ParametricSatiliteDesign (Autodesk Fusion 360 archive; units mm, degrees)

design "Assambly" references "SolarPanelWing", "SidePanelWithWingCutOut", "SidePanel", "TopandBottomPanel"
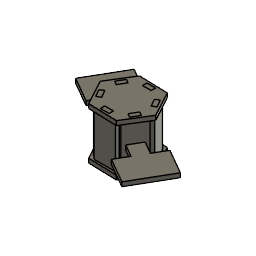
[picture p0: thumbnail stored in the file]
part number: 2026-03-25-13-54-13-246
component_insert "Component Insert1"
component_insert "Component Insert2"
joint "Assemble2" alignAngle 180 alignOffsetX 0 alignOffsetY -3 alignOffsetZ 0
component_insert "Component Insert3"
joint "Assemble3" alignAngle 180 alignOffsetX 0 alignOffsetY -3 alignOffsetZ 0
component_insert "Component Insert4"
joint "Assemble4" alignAngle 180 alignOffsetX 0 alignOffsetY -3 alignOffsetZ 0
component_insert "Component Insert6"
joint "Assemble6" alignAngle 180 alignOffsetX 0 alignOffsetY -3 alignOffsetZ 0
component_insert "Component Insert7"
joint "Assemble7" alignAngle 180 alignOffsetX 0 alignOffsetY -3 alignOffsetZ 0
component_insert "Component Insert9"
component_insert "Component Insert10"
joint "Assemble10" alignAngle 180 alignOffsetX 0 alignOffsetY -3 alignOffsetZ 0
component_insert "Component Insert11"
joint "Assemble11" alignAngle 180 alignOffsetX 0 alignOffsetY 0 alignOffsetZ 0
joint "Assemble12" alignAngle 0 alignOffsetX 0 alignOffsetY 3 alignOffsetZ 0
component_insert "Component Insert12"
joint "Assemble13" alignAngle -180 alignOffsetX 0 alignOffsetY 0 alignOffsetZ 0
component_insert "Component Insert13"
joint "Assemble14" alignAngle 0 alignOffsetX 0 alignOffsetY 0 alignOffsetZ 0

design "SidePanel"
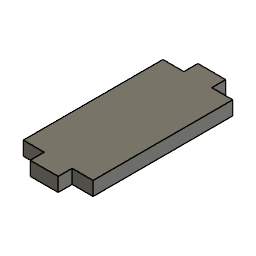
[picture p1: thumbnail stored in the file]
part number: 2026-03-25-13-26-19-886
parameter "BaseRectangleW" = 15
parameter "BaseRectangileH" = 30
parameter "MaterialThickness" = 3
parameter "JointW" = 6
sketch "Sketch1" plane through (0, 0, 0) normal (0, 1, 0) x axis (1, 0, 0)
  line L1 (15, 0) -> (0, 0)
  line L2 (15, 30) -> (15, 0)
  line L3 (0, 30) -> (15, 30)
  line L4 (0, 0) -> (0, 30)
  line L5 (10.5, 30) -> (4.5, 30)
  line L6 (10.5, 33) -> (10.5, 30)
  line L7 (4.5, 33) -> (10.5, 33)
  line L8 (4.5, 30) -> (4.5, 33)
  line L9 (10.5, 0) -> (4.5, 0)
  line L10 (10.5, -3) -> (10.5, 0)
  line L11 (4.5, -3) -> (10.5, -3)
  line L12 (4.5, 0) -> (4.5, -3)
  point P1 (0, 0)
  point P2 (0, 0)
  point P6 (4.5, 30)
  point P10 (4.5, 0)
  point P3 (15, 0)
  point P5 (0, 30)
  point P9 (4.5, 33)
  point P8 (10.5, 33)
  point P13 (4.5, -3)
  point P12 (10.5, -3)
  horizontal L1
  vertical L2
  horizontal L3
  vertical L4
  coincident P1 P2
  horizontal L5
  vertical L6
  horizontal L7
  vertical L8
  coincident L3 P6
  midpoint L3 L5
  horizontal L9
  vertical L10
  horizontal L11
  vertical L12
  coincident L1 P10
  midpoint L1 L9
  dimension "d5" distance P2 P3 = 15 (= "BaseRectangleW")
  dimension "d6" distance P2 P5 = 30 (= "BaseRectangileH")
  dimension "d7" distance P6 P9 = 3 (= "MaterialThickness")
  dimension "d8" distance P8 P9 = 6 (= "JointW")
  dimension "d9" distance P10 P13 = 3 (= "MaterialThickness")
  dimension "d10" distance P12 P13 = 6 (= "JointW")
extrude "Extrude1" new body sketch "Sketch1" along normal blind 3

design "TopandBottomPanel"
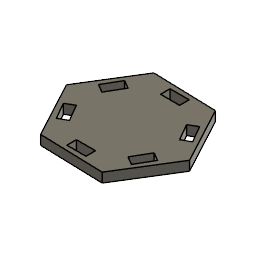
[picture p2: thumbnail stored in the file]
part number: 2026-03-25-13-47-20-194
parameter "PolygonSideW" = 20
parameter "MaterialThickness" = 3
sketch "Sketch1" plane through (0, 0, 0) normal (0, 1, 0) x axis (1, 0, 0)
  line L1 (19.9909, -0.602) -> (0, 0)
  line L2 (30.5078, 16.4096) -> (19.9909, -0.602)
  line L3 (21.0336, 34.0233) -> (30.5078, 16.4096)
  line L4 (1.0427, 34.6253) -> (21.0336, 34.0233)
  line L5 (-9.4741, 17.6137) -> (1.0427, 34.6253)
  line L6 (0, 0) -> (-9.4741, 17.6137)
  line L7 (10.0858, 2.699) -> (9.9955, -0.301)
  line L8 (7.0858, 4.199) -> (13.0858, 4.199)
  line L9 (7.0858, 1.199) -> (7.0858, 4.199)
  line L10 (13.0858, 1.199) -> (7.0858, 1.199)
  line L11 (13.0858, 4.199) -> (13.0858, 1.199)
  line L12 (7.0858, 1.199) -> (13.0858, 4.199)
  line L13 (13.0858, 1.199) -> (7.0858, 4.199)
  line L14 (22.8974, 12.8301) -> (25.4955, 11.3301)
  line L15 (25.4955, 11.3301) -> (22.4955, 6.134)
  line L16 (22.4955, 6.134) -> (19.8974, 7.634)
  line L17 (19.8974, 7.634) -> (22.8974, 12.8301)
  line L18 (20.3284, 25.6428) -> (22.9265, 27.1428)
  line L19 (22.9265, 27.1428) -> (25.9265, 21.9466)
  line L20 (25.9265, 21.9466) -> (23.3284, 20.4466)
  line L21 (23.3284, 20.4466) -> (20.3284, 25.6428)
  line L22 (7.9478, 29.8243) -> (7.9478, 32.8243)
  line L23 (7.9478, 32.8243) -> (13.9478, 32.8243)
  line L24 (13.9478, 32.8243) -> (13.9478, 29.8243)
  line L25 (13.9478, 29.8243) -> (7.9478, 29.8243)
  line L26 (-1.8638, 21.1932) -> (-4.4618, 22.6932)
  line L27 (-4.4618, 22.6932) -> (-1.4618, 27.8893)
  line L28 (-1.4618, 27.8893) -> (1.1362, 26.3893)
  line L29 (1.1362, 26.3893) -> (-1.8638, 21.1932)
  line L30 (0.7052, 8.3805) -> (-1.8928, 6.8805)
  line L31 (-1.8928, 6.8805) -> (-4.8928, 12.0767)
  line L32 (-4.8928, 12.0767) -> (-2.2948, 13.5767)
  line L33 (-2.2948, 13.5767) -> (0.7052, 8.3805)
  point P1 (0, 0)
  point P2 (0, 0)
  point P9 (9.9955, -0.301)
  point P15 (10.0858, 2.699)
  point P10 (10.0858, 2.699)
  point P3 (19.9909, -0.602)
  point P13 (7.0858, 1.199)
  point P14 (13.0858, 1.199)
  point P12 (7.0858, 4.199)
  coincident P1 P2
  coincident L1 P9
  perpendicular L1 L7
  midpoint L1 P9
  horizontal L8
  perpendicular L8 L9
  parallel L8 L10
  parallel L9 L11
  coincident L12 P15
  coincident L13 P15
  coincident P10 P15
  dimension "d3" distance P2 P3 = 20 (= "PolygonSideW")
  dimension "d4" distance P9 P10 = 3 (= "MaterialThickness")
  dimension "d6" distance P13 P14 = 6
  dimension "d7" distance P12 P13 = 3 (= "MaterialThickness")
  dimension "d11" C-Pattern1-Angle = 360
extrude "Extrude1" new body sketch "Sketch1" profile of L1 L2 L3 L4 L5 L6 L8 L9 L10 L11 L14 L15 L16 L17 L18 L19 L20 L21 L22 L23 L24 L25 L26 L27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 along normal blind 3

design "SolarPanelWing"
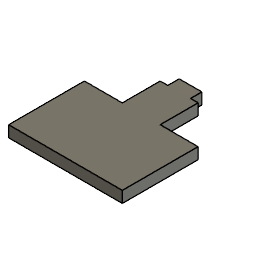
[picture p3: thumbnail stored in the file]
part number: 2026-03-25-13-26-19-886
parameter "BaseRectangleW" = 15
parameter "BaseRectangileH" = 30
parameter "MaterialThickness" = 3
parameter "JointW" = 6
sketch "Sketch1" plane through (0, 0, 0) normal (0, 1, 0) x axis (1, 0, 0)
  line L1 (10, 0) -> (0, 0)
  line L2 (10, 10) -> (10, 0)
  line L3 (0, 10) -> (10, 10)
  line L4 (0, 0) -> (0, 10)
  line L5 (8, 10) -> (2, 10)
  line L6 (8, 13) -> (8, 10)
  line L7 (2, 13) -> (8, 13)
  line L8 (2, 10) -> (2, 13)
  line L9 (8, 0) -> (2, 0)
  line L10 (-10, 0) -> (20, 0)
  line L11 (-10, -20) -> (-10, 0)
  line L12 (20, -20) -> (-10, -20)
  line L13 (20, 0) -> (20, -20)
  point P1 (0, 0)
  point P2 (0, 0)
  point P6 (2, 10)
  point P10 (2, 0)
  point P3 (10, 0)
  point P5 (0, 10)
  point P9 (2, 13)
  point P8 (8, 13)
  point P12 (20, 0)
  point P13 (-10, 0)
  point P15 (20, -20)
  horizontal L1
  vertical L2
  horizontal L3
  vertical L4
  coincident P1 P2
  horizontal L5
  vertical L6
  horizontal L7
  vertical L8
  coincident L3 P6
  midpoint L3 L5
  horizontal L9
  coincident L1 P10
  midpoint L1 L9
  horizontal L10
  vertical L11
  horizontal L12
  vertical L13
  midpoint L1 L10
  dimension "d5" distance P2 P3 = 10
  dimension "d6" distance P2 P5 = 10
  dimension "d7" distance P6 P9 = 3 (= "MaterialThickness")
  dimension "d8" distance P8 P9 = 6 (= "JointW")
  dimension "d15" distance P12 P13 = 30
  dimension "d16" distance P12 P15 = 20
  dimension "d13" distance = 6 (= "JointW")
  dimension "d14" distance = 3 (= "MaterialThickness")
extrude "Extrude1" new body sketch "Sketch1" along normal blind 3

design "SidePanelWithWingCutOut"
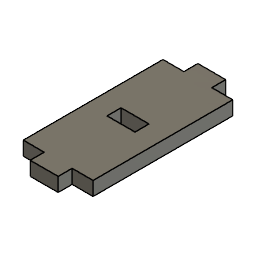
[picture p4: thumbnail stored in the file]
part number: 2026-03-25-13-26-19-886
parameter "BaseRectangleW" = 15
parameter "BaseRectangileH" = 30
parameter "MaterialThickness" = 3
parameter "JointW" = 6
sketch "Sketch1" plane through (0, 0, 0) normal (0, 1, 0) x axis (1, 0, 0)
  line L1 (15, 0) -> (0, 0)
  line L2 (15, 30) -> (15, 0)
  line L3 (0, 30) -> (15, 30)
  line L4 (0, 0) -> (0, 30)
  line L5 (10.5, 30) -> (4.5, 30)
  line L6 (10.5, 33) -> (10.5, 30)
  line L7 (4.5, 33) -> (10.5, 33)
  line L8 (4.5, 30) -> (4.5, 33)
  line L9 (10.5, 0) -> (4.5, 0)
  line L10 (10.5, -3) -> (10.5, 0)
  line L11 (4.5, -3) -> (10.5, -3)
  line L12 (4.5, 0) -> (4.5, -3)
  line L13 (7.5, 0) -> (7.5, 30)
  line L14 (15, 15) -> (0, 15)
  line L15 (4.5, 16.5) -> (10.5, 16.5)
  line L16 (4.5, 13.5) -> (4.5, 16.5)
  line L17 (10.5, 13.5) -> (4.5, 13.5)
  line L18 (10.5, 16.5) -> (10.5, 13.5)
  line L19 (4.5, 13.5) -> (10.5, 16.5)
  line L20 (10.5, 13.5) -> (4.5, 16.5)
  point P1 (0, 0)
  point P2 (0, 0)
  point P6 (4.5, 30)
  point P10 (4.5, 0)
  point P14 (7.5, 30)
  point P15 (7.5, 0)
  point P16 (0, 15)
  point P17 (15, 15)
  point P22 (7.5, 15)
  point P3 (15, 0)
  point P5 (0, 30)
  point P9 (4.5, 33)
  point P8 (10.5, 33)
  point P13 (4.5, -3)
  point P12 (10.5, -3)
  point P20 (4.5, 13.5)
  point P21 (10.5, 13.5)
  point P19 (4.5, 16.5)
  horizontal L1
  vertical L2
  horizontal L3
  vertical L4
  coincident P1 P2
  horizontal L5
  vertical L6
  horizontal L7
  vertical L8
  coincident L3 P6
  midpoint L3 L5
  horizontal L9
  vertical L10
  horizontal L11
  vertical L12
  coincident L1 P10
  midpoint L1 L9
  midpoint L3 P14
  midpoint L1 P15
  midpoint L4 P16
  midpoint L2 P17
  horizontal L15
  perpendicular L15 L16
  parallel L15 L17
  parallel L16 L18
  coincident L19 P22
  coincident L20 P22
  midpoint L13 P22
  dimension "d5" distance P2 P3 = 15 (= "BaseRectangleW")
  dimension "d6" distance P2 P5 = 30 (= "BaseRectangileH")
  dimension "d7" distance P6 P9 = 3 (= "MaterialThickness")
  dimension "d8" distance P8 P9 = 6 (= "JointW")
  dimension "d9" distance P10 P13 = 3 (= "MaterialThickness")
  dimension "d10" distance P12 P13 = 6 (= "JointW")
  dimension "d13" distance P20 P21 = 6 (= "JointW")
  dimension "d14" distance P19 P20 = 3 (= "MaterialThickness")
extrude "Extrude1" new body sketch "Sketch1" profile of L1 L2 L3 L4 L5 L6 L7 L8 L9 L10 L11 L12 L15 L16 L17 L18 along normal blind 3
